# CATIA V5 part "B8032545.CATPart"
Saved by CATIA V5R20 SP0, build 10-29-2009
Part number: B8032545
Revision: 7
Definition: design
Nomenclature: B8032545
Source: made
Description: NOT SPECIFIED
Bounding box of the stored display mesh (mm): x -20 to 20, y -20 to 20, z 0 to 45
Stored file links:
  C:\Users\Utente\Desktop\3D files B803\B8032545.CATPart
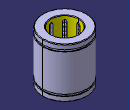
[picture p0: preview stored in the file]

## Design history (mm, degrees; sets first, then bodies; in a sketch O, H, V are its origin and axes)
Body1 "MANIFOLD_SOLID_BREP #38" (main body)
  Solid1: solid without history
Body2 "MANIFOLD_SOLID_BREP #76"
  Solid2: solid without history
Body3 "MANIFOLD_SOLID_BREP #114"
  Solid3: solid without history
Body4 "MANIFOLD_SOLID_BREP #152"
  Solid4: solid without history
Body5 "MANIFOLD_SOLID_BREP #190"
  Solid5: solid without history
Body6 "MANIFOLD_SOLID_BREP #228"
  Solid6: solid without history
Body7 "MANIFOLD_SOLID_BREP #266"
  Solid7: solid without history
Body8 "MANIFOLD_SOLID_BREP #304"
  Solid8: solid without history
Body9 "MANIFOLD_SOLID_BREP #2424"
  Solid9: solid without history
Body10 "MANIFOLD_SOLID_BREP #2462"
  Solid10: solid without history
Body11 "MANIFOLD_SOLID_BREP #2500"
  Solid11: solid without history
Body12 "MANIFOLD_SOLID_BREP #2538"
  Solid12: solid without history
Body13 "MANIFOLD_SOLID_BREP #2576"
  Solid13: solid without history
Body14 "MANIFOLD_SOLID_BREP #2614"
  Solid14: solid without history
Body15 "MANIFOLD_SOLID_BREP #2652"
  Solid15: solid without history
Body16 "MANIFOLD_SOLID_BREP #2690"
  Solid16: solid without history
Body17 "MANIFOLD_SOLID_BREP #2728"
  Solid17: solid without history
Body18 "MANIFOLD_SOLID_BREP #2766"
  Solid18: solid without history
Body19 "MANIFOLD_SOLID_BREP #2804"
  Solid19: solid without history
Body20 "MANIFOLD_SOLID_BREP #2842"
  Solid20: solid without history
Body21 "MANIFOLD_SOLID_BREP #2880"
  Solid21: solid without history
Body22 "MANIFOLD_SOLID_BREP #2918"
  Solid22: solid without history
Body23 "MANIFOLD_SOLID_BREP #2956"
  Solid23: solid without history
Body24 "MANIFOLD_SOLID_BREP #2994"
  Solid24: solid without history
Body25 "MANIFOLD_SOLID_BREP #3032"
  Solid25: solid without history
Body26 "MANIFOLD_SOLID_BREP #3070"
  Solid26: solid without history
Body27 "MANIFOLD_SOLID_BREP #3108"
  Solid27: solid without history
Body28 "MANIFOLD_SOLID_BREP #3146"
  Solid28: solid without history
Body29 "MANIFOLD_SOLID_BREP #3184"
  Solid29: solid without history
Body30 "MANIFOLD_SOLID_BREP #3222"
  Solid30: solid without history
Body31 "MANIFOLD_SOLID_BREP #3260"
  Solid31: solid without history
Body32 "MANIFOLD_SOLID_BREP #3298"
  Solid32: solid without history
Body33 "MANIFOLD_SOLID_BREP #3336"
  Solid33: solid without history
Body34 "MANIFOLD_SOLID_BREP #3374"
  Solid34: solid without history
Body35 "MANIFOLD_SOLID_BREP #3412"
  Solid35: solid without history
Body36 "MANIFOLD_SOLID_BREP #3450"
  Solid36: solid without history
Body37 "MANIFOLD_SOLID_BREP #3488"
  Solid37: solid without history
Body38 "MANIFOLD_SOLID_BREP #3526"
  Solid38: solid without history
Body39 "MANIFOLD_SOLID_BREP #3564"
  Solid39: solid without history
Body40 "MANIFOLD_SOLID_BREP #3602"
  Solid40: solid without history
Body41 "MANIFOLD_SOLID_BREP #3640"
  Solid41: solid without history
Body42 "MANIFOLD_SOLID_BREP #3678"
  Solid42: solid without history
Body43 "MANIFOLD_SOLID_BREP #3716"
  Solid43: solid without history
Body44 "MANIFOLD_SOLID_BREP #3754"
  Solid44: solid without history
Body45 "MANIFOLD_SOLID_BREP #3792"
  Solid45: solid without history
Body46 "MANIFOLD_SOLID_BREP #3830"
  Solid46: solid without history
Body47 "MANIFOLD_SOLID_BREP #3868"
  Solid47: solid without history
Body48 "MANIFOLD_SOLID_BREP #3906"
  Solid48: solid without history
Body49 "MANIFOLD_SOLID_BREP #3944"
  Solid49: solid without history
Body50 "MANIFOLD_SOLID_BREP #3982"
  Solid50: solid without history
Body51 "MANIFOLD_SOLID_BREP #4020"
  Solid51: solid without history
Body52 "MANIFOLD_SOLID_BREP #4058"
  Solid52: solid without history
Body53 "MANIFOLD_SOLID_BREP #4096"
  Solid53: solid without history
Body54 "MANIFOLD_SOLID_BREP #4134"
  Solid54: solid without history
Body55 "MANIFOLD_SOLID_BREP #4172"
  Solid55: solid without history
Body56 "MANIFOLD_SOLID_BREP #4210"
  Solid56: solid without history
Body57 "MANIFOLD_SOLID_BREP #4248"
  Solid57: solid without history
Body58 "MANIFOLD_SOLID_BREP #4286"
  Solid58: solid without history
Body59 "MANIFOLD_SOLID_BREP #4324"
  Solid59: solid without history
Body60 "MANIFOLD_SOLID_BREP #4362"
  Solid60: solid without history
Body61 "MANIFOLD_SOLID_BREP #4400"
  Solid61: solid without history
Body62 "MANIFOLD_SOLID_BREP #4438"
  Solid62: solid without history
Body63 "MANIFOLD_SOLID_BREP #4476"
  Solid63: solid without history
Body64 "MANIFOLD_SOLID_BREP #4514"
  Solid64: solid without history
Body65 "MANIFOLD_SOLID_BREP #4552"
  Solid65: solid without history
Body66 "MANIFOLD_SOLID_BREP #4590"
  Solid66: solid without history
Body67 "MANIFOLD_SOLID_BREP #4628"
  Solid67: solid without history
Body68 "MANIFOLD_SOLID_BREP #4666"
  Solid68: solid without history
Body69 "MANIFOLD_SOLID_BREP #4704"
  Solid69: solid without history
Body70 "MANIFOLD_SOLID_BREP #4742"
  Solid70: solid without history
Body71 "MANIFOLD_SOLID_BREP #4780"
  Solid71: solid without history
Body72 "MANIFOLD_SOLID_BREP #4818"
  Solid72: solid without history
Body73 "MANIFOLD_SOLID_BREP #4856"
  Solid73: solid without history
Body74 "MANIFOLD_SOLID_BREP #4894"
  Solid74: solid without history
Body75 "MANIFOLD_SOLID_BREP #4932"
  Solid75: solid without history
Body76 "MANIFOLD_SOLID_BREP #4970"
  Solid76: solid without history
Body77 "MANIFOLD_SOLID_BREP #5008"
  Solid77: solid without history
Body78 "MANIFOLD_SOLID_BREP #5046"
  Solid78: solid without history
Body79 "MANIFOLD_SOLID_BREP #5084"
  Solid79: solid without history
Body80 "MANIFOLD_SOLID_BREP #5122"
  Solid80: solid without history
Body81 "MANIFOLD_SOLID_BREP #5160"
  Solid81: solid without history
Body82 "MANIFOLD_SOLID_BREP #5198"
  Solid82: solid without history
Body83 "MANIFOLD_SOLID_BREP #5236"
  Solid83: solid without history
Body84 "MANIFOLD_SOLID_BREP #5274"
  Solid84: solid without history
Body85 "MANIFOLD_SOLID_BREP #5312"
  Solid85: solid without history
Body86 "MANIFOLD_SOLID_BREP #5350"
  Solid86: solid without history
Body87 "MANIFOLD_SOLID_BREP #5388"
  Solid87: solid without history
Body88 "MANIFOLD_SOLID_BREP #5426"
  Solid88: solid without history
Body89 "MANIFOLD_SOLID_BREP #5464"
  Solid89: solid without history
Body90 "MANIFOLD_SOLID_BREP #5502"
  Solid90: solid without history
Body91 "MANIFOLD_SOLID_BREP #5540"
  Solid91: solid without history
Body92 "MANIFOLD_SOLID_BREP #5578"
  Solid92: solid without history
Body93 "MANIFOLD_SOLID_BREP #5616"
  Solid93: solid without history
Body94 "MANIFOLD_SOLID_BREP #5654"
  Solid94: solid without history
Body95 "MANIFOLD_SOLID_BREP #5692"
  Solid95: solid without history
Body96 "MANIFOLD_SOLID_BREP #5730"
  Solid96: solid without history
Body97 "MANIFOLD_SOLID_BREP #5768"
  Solid97: solid without history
